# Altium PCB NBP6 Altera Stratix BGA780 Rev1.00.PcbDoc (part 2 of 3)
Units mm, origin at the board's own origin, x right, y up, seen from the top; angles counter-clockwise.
Board outline 69 x 80.99 mm, 6 copper layers (Top Layer, Upper, lower, VCC_PLANE, GND_PLANE, Bottom Layer); 92 components, 279 nets, 1271 pads, 560 vias.
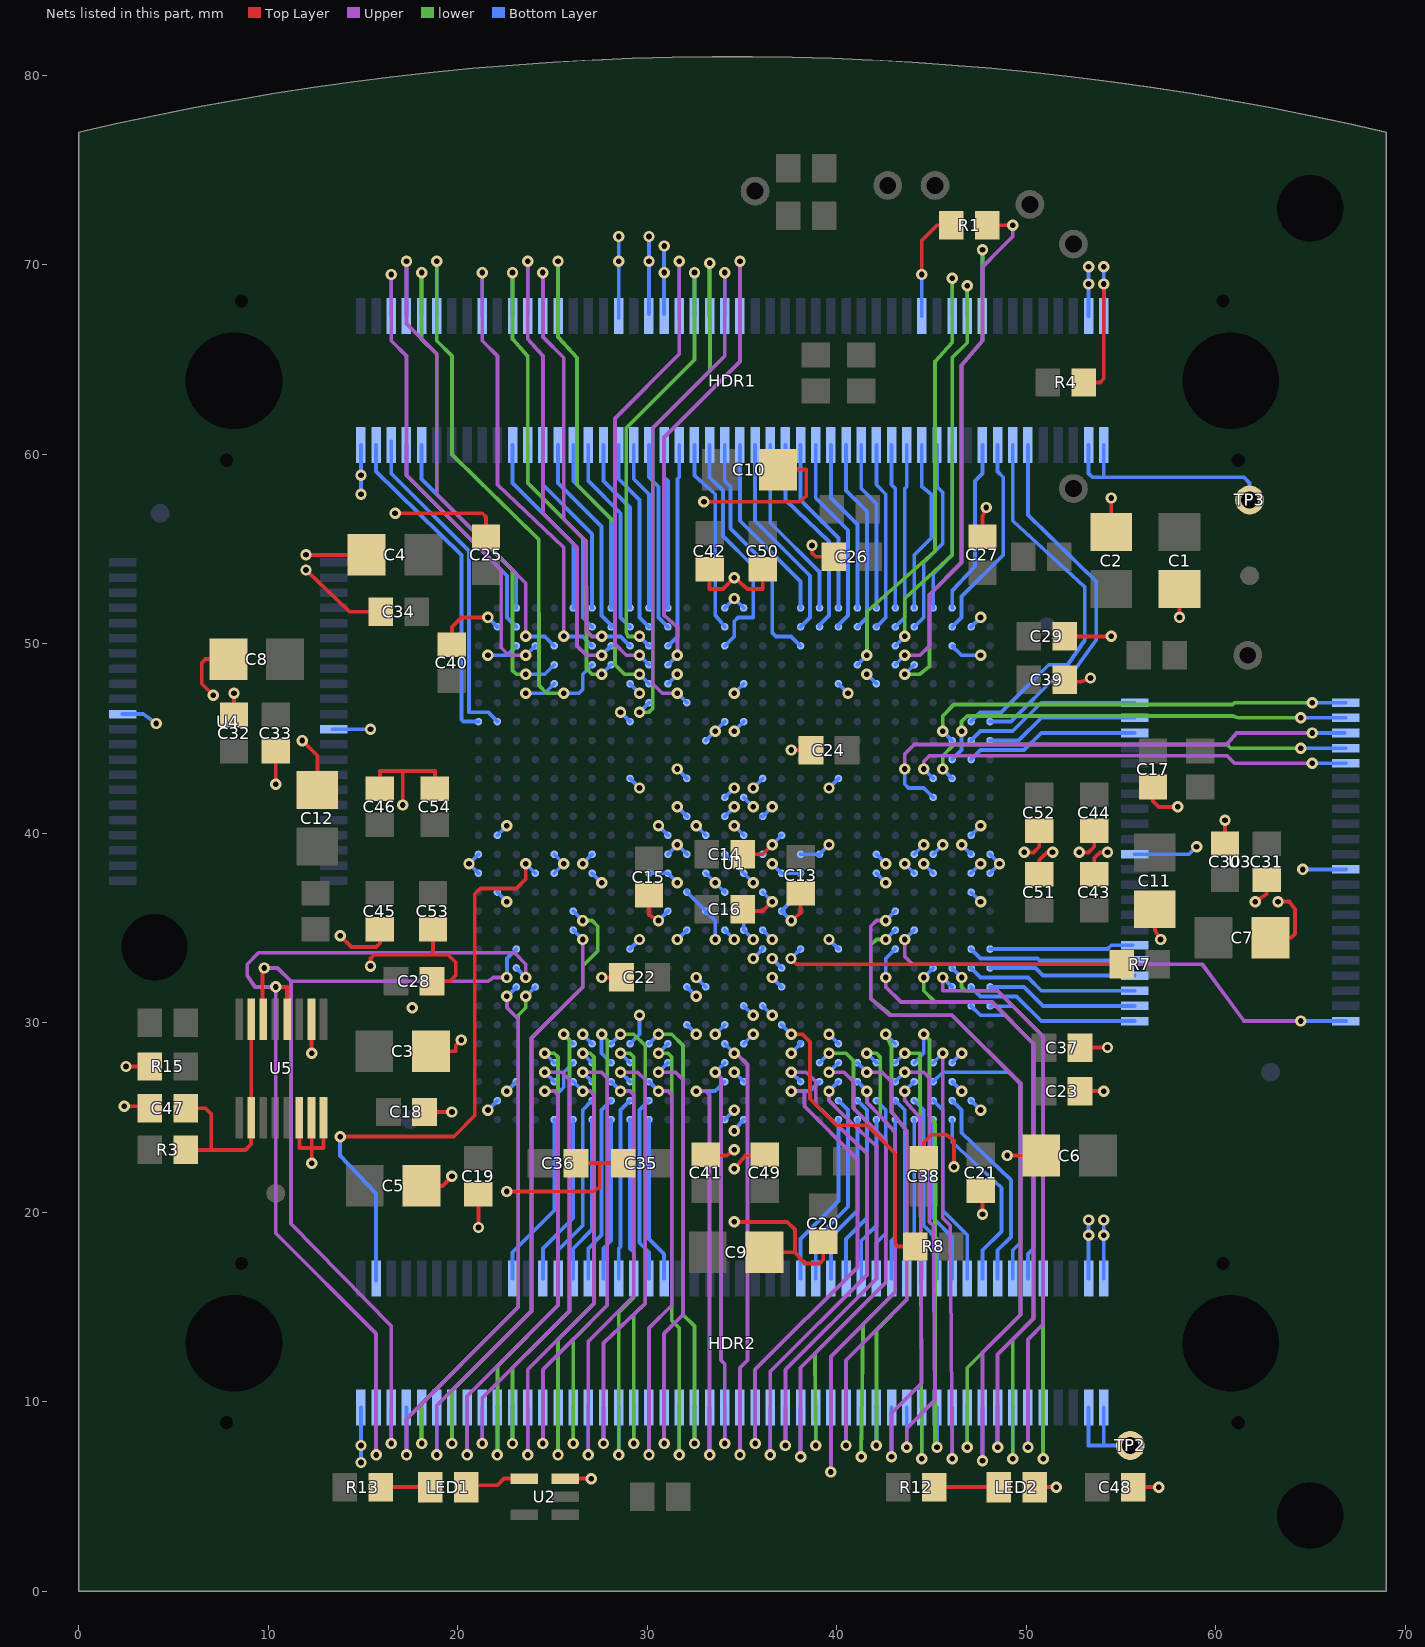
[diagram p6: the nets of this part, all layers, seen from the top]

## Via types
v1: diameter 0.6, hole 0.3, Top Layer to Bottom Layer, 560 vias

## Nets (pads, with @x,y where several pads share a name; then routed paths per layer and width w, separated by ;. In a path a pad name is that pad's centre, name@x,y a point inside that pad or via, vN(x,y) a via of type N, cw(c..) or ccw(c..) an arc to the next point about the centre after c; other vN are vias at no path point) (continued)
GND: C1.2 C2.2 C3.2 C4.2 C5.2 C6.2 C7.2 C8.2 C9.2 C10.2 C11.2 C12.2 C13.2 C14.2 C15.2 C16.2 C17.2 C18.2 C19.2 C20.2 C21.2 C22.2 C23.2 C24.2 C25.2 C26.2 C27.2 C28.2 C29.2 C30.2 C31.2 C32.2 C33.2 C34.2 C35.2 C36.2 C37.2 C38.2 C39.2 C40.2 C41.2 C42.2 C43.2 C44.2 C45.2 C46.2 C47.2 C48.2 C49.2 C50.2 C51.2 C52.2 C53.2 C54.2 HDR1.1 HDR1.36 HDR1.40 HDR1.42 HDR1.98 HDR1.100 HDR2.1 HDR2.98 HDR2.100 LED2.2 R4.2 R15.1 U1.A14 U1.A15 U1.AA12 U1.AA16 U1.AA17 U1.AB13 U1.AB14 U1.AC15 U1.AC17 U1.AD9 U1.AD11 U1.AD14 U1.AD20 U1.AD22 U1.AE3 U1.AF3 U1.AF14 U1.AF26 U1.AG2 U1.AG27 U1.AH14 U1.AH15 U1.B2 U1.B27 U1.C3 U1.C26 U1.E7 U1.E9 U1.E14 U1.E18 U1.E20 U1.E24 U1.G14 U1.G15 U1.G20 U1.H16 U1.K9 U1.K13 U1.K17 U1.K20 U1.L14 U1.L15 U1.M13 U1.M15 U1.M17 U1.N2 U1.N12 U1.N14 U1.N16 U1.N18 U1.N27 U1.P1 U1.P2 U1.P4 U1.P5 U1.P7 U1.P10 U1.P11 U1.P13 U1.P15 U1.P17 U1.P18 U1.P22 U1.P24 U1.P28 U1.R1 U1.R2 U1.R4 U1.R5 U1.R7 U1.R11 U1.R12 U1.R14 U1.R16 U1.R18 U1.R19 U1.R22 U1.R24 U1.R28 U1.T2 U1.T11 U1.T13 U1.T15 U1.T17 U1.T27 U1.U12 U1.U14 U1.U16 U1.U18 U1.V13 U1.V14 U1.V15 U1.V17 U1.W9 U1.W13 U1.W20 U1.Y12 U2.3 U3.12 U3.34 U4.12 U4.34 U5.6 U5.7 U5.8 U5.10 | length 273.2
  Top Layer w0.2: v1(2.4,25.6) C47.2@3.7,25.6 ; v1(2.5,27.7) R15.1@3.75,27.7 ; v1(7.1,47.3) 6.5,47.9 6.5,49 6.7,49.2 C8.2@7.9,49.2 ; C32.2@8.2,46.25 8.2,47.1 v1(8.2,47.4) ; v1@10.4,42.8 C33.2@10.4,44.4 ; U5.6@11.652,25 11.652,23.4 12.9,23.4 12.922,23.422 U5.8@12.922,25 ; v1(11.8,44.9) 12.6,44.1 C12.2@12.6,42.4 ; v1(12,54.7) C4.2@15.2,54.7 ; v1@12.2,53.9 v1(12,53.9) 14.3,51.7 C34.2@15.95,51.7 ; v1(12.3,22.6) U5.7@12.3,25 ; v1(12.3,28.4) 12.287,28.413 U5.10@12.287,30.2 U5.10@12.3,30.213 ; v1(13.8,34.6) 14.4,34 15.7,34 15.9,34.2 C45.2@15.9,35 ; v1@15.4,32.9 15.4,33.4 15.6,33.6 19.5,33.6 19.9,33.2 19.9,32.5 19.6,32.2 C28.2@18.65,32.2 ; C34.2@15.4,51.1 C34.2@16.35,51.1 ; C46.2@15.9,42.35 15.9,43.3 18.8,43.3 C54.2@18.8,42.35 ; v1(16.7,56.9) 21.3,56.9 21.5,56.7 ; v1(17.1,41.5) 17.1,43.3 ; C5.2@18.1,21.4 19.2,21.4 v1(19.7,21.9) ; C18.2@18.2,25.3 v1(19.7,25.3) ; C3.2@18.6,28.5 19.9,28.5 19.9,28.8 v1(20.2,29.1) ; 18.7,33.6 C53.2@18.7,34.95 C53.2@18.7,34.9 ; C40.2@19.7,49.95 19.7,50.9 20.2,51.4 v1(21.6,51.4) ; v1(21.1,19.2) 21.1,20.9 C19.2@21.1,20.95 ; C25.2@21.5,55.85 21.5,56.7 ; 21.5,56.5 21.5,56.7 ; v1(22.6,21.1) 27.1,21.1 27.5,21.3 27.5,22.6 ; U2.3@25.675,5.95 v1(27.05,5.95) ; C36.2@26.25,22.6 27.5,22.6 ; 27.1,22.6 27.5,22.6 ; v1(27.6,32.4) C22.2@28.65,32.4 ; C35.2@28.75,22.6 27.5,22.6 ; C15.2@30.1,36.75 30.1,35.7 v1(30.6,35.4) ; v1(33,57.5) 38,57.5 38.4,57.8 38.4,59.2 C10.2@36.9,59.2 ; C41.2@33.1,23 34.2,23 v1(34.6,23.3) v1@34.6,23.4 ; C42.2@33.3,53.95 33.3,52.9 34,52.9 v1(34.6,53.5) ; v1@34.6,19.6 v1(34.6,19.5) 37.4,19.5 37.8,19.1 37.8,17.9 ; v1(34.6,22.3) 35.2,23 C49.2@36.2,23 ; v1@34.7,53.5 v1(34.6,53.5) ; C16.2@35.05,35.9 36.1,35.9 v1(36.6,36.4) ; C14.2@35.05,38.9 36.1,38.9 v1(36.6,39.4) ; C50.2@36.1,53.95 36.1,52.9 35.3,52.9 v1(34.6,53.5) ; C9.2@36.2,17.9 37.8,17.9 ; v1(37.6,35.4) 38.1,35.8 C13.2@38.1,36.85 ; v1(37.6,44.4) C24.2@38.7,44.4 ; v1(38.7,55.2) 38.7,54.8 38.9,54.6 C26.2@39.85,54.6 ; C20.2@39.3,18.45 39.3,17.5 39.1,17.3 38.3,17.3 37.8,17.9 ; C38.2@44.6,22.85 44.6,23.7 45,24.1 45.8,24.1 46.2,23.8 v1(46.2,22.4) ; v1(47.7,19.9) C21.2@47.7,21 ; C27.2@47.7,55.6 47.7,56.7 v1(47.9,57.2) ; v1(49,23) C6.2@50.7,23 ; v1(49.9,39) 50.4,39 50.7,39.3 C52.2@50.7,40.15 ; LED2.2@50.45,5.5 v1(51.6,5.5) ; C51.2@50.7,37.85 50.7,38.6 51.1,39 v1(51.4,39) ; C39.2@52,48 52.9,48 v1(53.4,48.2) ; C29.2@52.05,50.4 v1@54.2,50.4 ; C37.2@52.4,28.7 v1(54.3,28.7) ; v1(52.8,39) 53.3,39 53.6,39.3 C44.2@53.6,40.2 ; C23.2@52.85,26.4 v1(54.1,26.4) ; R4.2@53.05,63.8 53.9,63.8 54.1,64 v1(54.1,69) ; C43.2@53.6,37.85 53.6,38.7 53.9,39 v1(54.3,39) ; C2.2@54.5,55.9 v1(54.5,57.7) ; C48.2@55.6,5.5 v1(57,5.5) ; C17.2@56.7,42.4 56.7,41.7 57,41.4 v1(58,41.4) ; C11.2@56.8,36 56.8,34.9 v1(57.1,34.4) ; v1(58.1,51.4) C1.2@58.1,52.9 ; C30.2@60.5,39.4 v1(60.5,40.7) ; v1(62.1,36.4) 62.7,36.8 C31.2@62.7,37.55 ; C7.2@62.9,34.5 64,34.5 64.2,34.7 64.2,36 63.9,36.4 v1(63.3,36.4)
  Upper w0.2: v1(27.05,5.95) v1@27.1,6
  Bottom Layer w0.2: U4.34@2.3,46.3 3.4,46.3 v1(4.1,45.8) ; U4.12@13.4,45.5 v1(15.4,45.5) ; v1(14.9,6.8) v1(14.9,7.7) HDR2.1@14.9,9.7 ; v1(14.9,57.9) HDR1.1@14.9,60.5 ; U1.R28@21.1,37.9 v1(20.6,38.4) U1.P28@21.1,38.9 ; v1(21.6,25.4) U1.AG27@22.1,25.9 ; v1(21.6,49.4) 22.6,49.4 U1.C26@23.1,49.9 ; v1(21.6,51.4) U1.B27@22.1,50.9 ; U1.T27@22.1,36.9 v1(22.6,36.4) ; U1.N27@22.1,39.9 v1(22.6,40.4) ; v1(22.6,26.4) U1.AF26@23.1,26.9 ; v1(23.6,47.4) 24.6,47.4 U1.E24@25.1,47.9 ; U1.R24@25.1,37.9 v1(25.6,38.4) U1.P24@25.1,38.9 ; v1(26.6,29.4) U1.AD22@27.1,28.9 ; v1(26.6,38.4) U1.P22@27.1,38.9 ; U1.R22@27.1,37.9 v1(27.6,37.4) ; HDR1.36@28.5,67.2 v1(28.5,71.5) ; v1(28.6,46.4) U1.G20@29.1,45.9 ; U1.AD20@29.1,28.9 29.6,29.4 v1(29.6,30.4) ; U1.W20@29.1,33.9 v1(29.6,34.4) ; U1.K20@29.1,42.9 v1(29.6,42.4) ; U1.E20@29.1,47.9 v1(29.6,47.4) ; U1.R19@30.1,37.9 U1.R18@31.1,37.9 v1(31.6,37.4) ; HDR1.40@30.1,67.4 v1(30.1,71.5) ; v1(30.6,35.4) U1.U18@31.1,35.9 ; v1(30.6,40.4) U1.N18@31.1,39.9 ; HDR1.42@30.9,67.4 v1(30.9,71) ; U1.P18@31.1,38.9 v1(31.6,39.4) U1.P17@32.1,38.9 ; U1.E18@31.1,47.9 v1(31.6,48.4) ; v1(31.6,34.4) U1.V17@32.1,34.9 ; v1(31.6,41.4) U1.M17@32.1,40.9 ; v1(31.6,43.4) U1.K17@32.1,42.9 ; U1.AC17@32.1,29.9 v1(32.6,29.4) ; U1.AA17@32.1,31.9 v1(32.6,31.4) ; U1.T17@32.1,37 U1.T17@32.1,36.9 U1.U16@33.1,35.9 ; v1(32.6,32.4) U1.AA16@33.1,31.9 ; v1(32.6,40.4) U1.N16@33.1,39.9 ; U1.U16@33.1,35.8 U1.U16@33.1,35.9 ; U1.R16@33.1,37.9 v1(33.6,37.4) U1.T15@34.1,36.9 U1.T15@34.1,37 ; U1.H16@33.1,44.9 v1(33.6,45.4) U1.G15@34.1,45.9 ; v1(33.6,29.4) U1.AC15@34.1,29.9 ; v1(33.6,34.4) 33.6,35.3 33.6,35.4 U1.U16@33.1,35.9 ; U1.AH15@34.1,24.9 v1(34.6,25.4) ; U1.V15@34.1,34.9 v1(34.6,34.4) ; U1.P15@34.1,38.9 U1.R14@35.1,37.9 v1@35.5,37.5 ; U1.M15@34.1,40.9 v1(34.6,41.4) ; U1.L15@34.1,41.9 v1(34.6,42.4) ; U1.A15@34.1,51.9 v1(34.6,52.4) U1.A14@35.1,51.9 ; v1(34.6,24.3) U1.AH14@35.1,24.9 ; v1(34.6,27.4) U1.AF14@35.1,26.9 ; v1(34.6,40.4) U1.N14@35.1,39.9 ; v1(34.6,45.4) U1.G14@35.1,45.9 ; v1(34.6,47.4) U1.E14@35.1,47.9 ; U1.AD14@35.1,28.9 v1(35.6,29.4) ; U1.AB14@35.1,30.9 v1(35.6,30.4) ; U1.U14@35.1,35.9 U1.V14@35.1,34.9 v1(35.6,34.4) ; U1.L14@35.1,41.9 v1(35.6,41.4) ; v1(35.6,33.4) U1.W13@36.1,33.9 ; v1(35.6,42.4) U1.K13@36.1,42.9 ; U1.M13@36,40.9 U1.M13@36.1,40.9 v1(36.6,41.4) ; U1.AB13@36.1,30.9 v1(36.6,30.4) ; U1.V13@36.1,34.9 v1(36.6,34.4) ; U1.T13@36.1,36.9 v1(36.6,36.4) ; U1.P13@36.1,38.9 v1(36.6,39.4) ; v1(36.6,32.4) U1.AA12@37.1,31.9 ; v1(36.6,33.4) U1.Y12@37.1,32.9 ; v1(36.6,38.4) U1.R12@37.1,37.9 ; v1@36.6,39.5 v1(36.6,39.4) ; U1.N12@37,39.8 v1(36.6,39.4) ; U1.R12@37.2,37.9 U1.R12@37.1,37.9 ; v1(37.6,28.4) U1.AD11@38.1,28.9 ; v1(37.6,35.4) U1.U12@37.1,35.9 U1.T11@38.1,36.9 ; U1.AD11@38,28.9 U1.AD11@38.1,29 ; U1.R11@38,37.9 U1.R11@38.1,37.9 ; U1.P11@38.1,38.9 U1.P10@39.1,38.9 ; U1.R11@38.2,37.9 U1.R11@38.1,37.9 ; U1.P10@39.1,38.8 U1.P10@39.1,38.9 ; v1(39.6,29.4) U1.AD9@40.1,28.9 ; v1(39.6,34.4) U1.W9@40.1,33.9 ; v1(39.6,39.4) U1.P10@39.1,38.9 ; v1(39.6,42.4) U1.K9@40.1,42.9 ; U1.E9@40.1,47.9 v1(40.6,47.4) ; v1(41.6,48.4) U1.E7@42.1,47.9 ; U1.R7@42.1,37.9 v1(42.6,37.4) ; U1.P7@42.1,38.9 v1(42.6,38.4) ; v1(43.6,38.4) U1.R5@44.1,37.9 ; U1.P5@44.1,38.9 v1(44.6,39.4) ; v1(44.6,38.4) U1.R4@45.1,37.9 ; U1.P4@45.1,38.9 v1(45.6,39.4) ; U1.AF3@46.1,26.9 v1(46.6,26.4) ; U1.AE3@46.1,27.9 v1(46.6,28.4) ; U1.C3@46.2,49.9 U1.C3@46.1,49.9 46.6,49.4 v1(47.6,49.4) ; v1(46.6,39.4) U1.P2@47.1,38.9 U1.P2@47.1,39 ; U1.AG2@47.1,25.9 v1(47.6,25.4) ; U1.T2@47.1,36.9 v1(47.6,36.4) ; U1.R2@47.1,37.9 v1(47.6,38.4) ; U1.N2@47.1,39.9 v1(47.6,40.4) ; U1.B2@47.1,50.9 v1(47.6,51.4) ; U1.R1@48.1,37.9 v1(48.6,38.4) U1.P1@48.1,38.9 ; HDR2.98@53.3,16.5 v1(53.3,19.6) ; HDR1.98@53.3,67.3 v1(53.3,69.9) ; HDR2.100@54.1,16.5 v1(54.1,19.6) ; HDR1.100@54.1,67.4 v1(54.1,69.9) ; U3.34@55.725,38.9 58.6,38.9 v1(59,39.3) ; v1(64.6,38.1) U3.12@66.9,38.1 ; U1.W13@36.1,33.9 36.1,34 U1.W13@36.1,33.9 ; U1.R12@37.1,37.9 U1.R11@38.1,37.9 ; U1.N12@37,39.9 U1.N12@37.1,39.9 U1.N12@37,39.9
  other v1: 53.3,18.8 54.1,18.8 17.6,30.8 15.4,33 35.6,37.4 10.4,42.6 54.5,50.4 14.9,58.9 53.3,69 30.9,69.6 28.5,70.2 30.1,70.2
GREEN0: HDR1.10 U1.D24 | length 27.7
  lower w0.2: v1(18.1,69.6) 18.1,66.1 18.9,65.3 18.9,57.9 22.9,53.9 22.9,48.6 23.1,48.4 v1(23.6,48.4)
  Bottom Layer w0.2: HDR1.10@18.1,67.4 v1(18.1,69.6) ; v1(23.6,48.4) 24.6,48.4 U1.D24@25.1,48.9
GREEN1: HDR1.12 U1.D22 | length 31.6
  lower w0.2: v1(18.9,70.2) 18.9,66 19.7,65.2 19.7,60 24.283,55.517 24.3,47.8 24.7,47.4 v1(25.6,47.4)
  Bottom Layer w0.2: HDR1.12@18.9,67.3 v1(18.9,70.2) ; v1(25.6,47.4) 26.4,47.4 26.6,47.6 26.6,48.4 U1.D22@27.1,48.9
HDRIVE: HDR1.18 U1.C22 | length 25
  Upper w0.2: v1(21.3,69.6) 21.3,66 22.1,65.2 22.1,58.4 25.6,55.1 v1(25.6,50.4)
  Bottom Layer w0.2: HDR1.18@21.3,67.3 v1(21.3,69.6) ; v1(25.6,50.4) 26.6,50.4 U1.C22@27.1,49.9
INIT_DONE: R7.2 U1.W11 | length 18.3
  Top Layer w0.2: v1(37.592,33.401) 37.893,33.1 R7.2@55.05,33.1
  Bottom Layer w0.2: v1(37.592,33.401) v1@37.633,33.441 ; v1@37.637,33.437 U1.W11@38.1,33.9
IO0: HDR2.7 U1.AA26 | length 30.1
  Upper w0.2: v1(17.3,7.2) 17.3,9.1 23.2,15 23.2,30.2 22.6,30.8 v1(22.6,31.4)
  Bottom Layer w0.2: v1(17.3,7.2) HDR2.7@17.3,9.7 ; v1(22.6,31.4) U1.AA26@23.1,31.9
IO1: HDR2.9 U1.AA25 | length 28.4
  lower w0.2: v1(18.1,7.8) 18.1,9.9 23.2,15 23.2,15.3 23.2,30.4 23.6,30.8 v1(23.6,31.4)
  Bottom Layer w0.2: v1(18.1,7.8) HDR2.9@18.1,9.6 ; v1(23.6,31.4) U1.AA25@24.1,31.9
IO2: HDR2.11 U1.V23 | length 33.6
  Upper w0.2: v1(18.9,7.2) 18.9,9.8 23.9,14.8 23.9,29.2 26.6,31.9 v1(26.6,34.4)
  Bottom Layer w0.2: v1(18.9,7.2) HDR2.11@18.9,9.7 ; U1.V23@26.1,34.9 v1(26.6,34.4)
IO3: HDR2.13 U1.U23 | length 34
  lower w0.2: v1(19.7,7.8) 19.7,10.6 23.9,14.8 23.9,29.2 26.6,31.9 26.6,33 27.4,33.8 27.4,35.1 27.1,35.4 v1(26.6,35.4)
  Bottom Layer w0.2: v1(19.7,7.8) HDR2.13@19.7,9.7 ; U1.U23@26.1,35.9 v1(26.6,35.4)
IO4: HDR2.15 U1.AE23 | length 26.9
  Upper w0.2: v1(20.5,7.2) 20.5,10.3 25.3,15.1 25.3,26.2 25.1,26.4 v1(24.6,26.4)
  Bottom Layer w0.2: v1(20.5,7.2) HDR2.15@20.5,9.7 ; v1(24.6,26.4) 25.4,26.4 25.6,26.6 25.6,27.4 U1.AE23@26.1,27.9
IO5: HDR2.17 U1.AF24 | length 25.2
  Upper w0.2: v1(21.3,7.8) 21.3,10.2 25.9,14.8 25.9,27 25.5,27.4 v1(24.6,27.4)
  Bottom Layer w0.2: v1(21.3,7.8) HDR2.17@21.3,9.7 ; v1(24.6,27.4) U1.AF24@25.1,26.9
IO6: HDR2.19 U1.AE24 | length 26.3
  lower w0.2: v1(22.1,7.2) 22.1,11.9 25.3,15.1 25.3,28.2 25.1,28.4 v1(24.6,28.4)
  Bottom Layer w0.2: v1(22.1,7.2) HDR2.19@22.1,9.7 ; v1(24.6,28.4) U1.AE24@25.1,27.9
IO7: HDR2.21 U1.AD23 | length 25.6
  lower w0.2: v1(22.9,7.8) 22.9,11.8 25.9,14.8 25.9,29.1 v1(25.6,29.4)
  Bottom Layer w0.2: v1(22.9,7.8) HDR2.21@22.9,9.7 ; v1(25.6,29.4) U1.AD23@26.1,28.9
IO8: HDR2.23 U1.AF23 | length 24.3
  Upper w0.2: v1(23.7,7.2) 23.7,11.7 27.2,15.2 27.2,26.2 27,26.4 v1(26.6,26.4)
  Bottom Layer w0.2: v1(23.7,7.2) HDR2.23@23.7,9.7 ; U1.AF23@26.1,26.9 v1(26.6,26.4)
IO9: HDR2.25 U1.AF22 | length 24.7
  Upper w0.2: v1(24.5,7.8) 24.5,11.7 27.9,15.1 27.9,27.1 27.6,27.4 v1(26.6,27.4)
  Bottom Layer w0.2: v1(24.5,7.8) HDR2.25@24.5,9.7 ; v1(26.6,27.4) U1.AF22@27.1,26.9
IO10: HDR2.27 U1.AE22 | length 25.8
  lower w0.2: v1(25.3,7.2) 25.3,13.3 27.2,15.2 27.2,28.2 27,28.4 v1(26.6,28.4)
  Bottom Layer w0.2: v1(25.3,7.2) HDR2.27@25.3,9.8 ; v1(26.6,28.4) U1.AE22@27.1,27.9
IO11: HDR2.29 U1.AE21 | length 26.1
  lower w0.2: v1(26.1,7.8) 26.1,13.3 27.9,15.1 27.9,29.1 v1(27.6,29.4)
  Bottom Layer w0.2: v1(26.1,7.8) HDR2.29@26.1,9.7 ; v1(27.6,29.4) 27.6,28.4 U1.AE21@28.1,27.9
IO12: HDR2.31 U1.AF21 | length 24.1
  Upper w0.2: v1(26.9,7.2) 26.9,13.2 29.3,15.6 29.3,26.2 29.1,26.4 v1(28.6,26.4)
  Bottom Layer w0.2: v1(26.9,7.2) HDR2.31@26.9,9.8 ; U1.AF21@28.1,26.9 v1(28.6,26.4)
IO13: HDR2.33 U1.AF20 | length 24.2
  Upper w0.2: v1(27.7,7.8) 27.7,13.1 29.9,15.2 29.9,27 29.5,27.4 v1(28.6,27.4)
  Bottom Layer w0.2: v1(27.7,7.8) HDR2.33@27.7,9.7 ; v1(28.6,27.4) U1.AF20@29.1,26.9
IO14: HDR2.35 U1.AE20 | length 25.3
  lower w0.2: v1(28.5,7.2) 28.5,14.7 29.3,15.5 29.3,28.2 29.1,28.4 v1(28.6,28.4)
  Bottom Layer w0.2: v1(28.5,7.2) HDR2.35@28.5,9.7 ; v1(28.6,28.4) U1.AE20@29.1,27.9
IO15: HDR2.37 U1.AD21 | length 25.5
  lower w0.2: v1(28.6,29.4) 29.3,29.4 29.9,28.8 29.9,15.2 29.3,14.6 v1(29.3,7.8)
  Bottom Layer w0.2: U1.AD21@28.1,28.9 v1(28.6,29.4) ; v1(29.3,7.8) HDR2.37@29.3,9.8
IO16: HDR2.39 U1.AF19 | length 23.5
  Upper w0.2: v1(30.1,7.2) 30.1,13.9 31.3,15.1 31.3,26.2 31.1,26.4 v1(30.6,26.4)
  Bottom Layer w0.2: v1(30.1,7.2) HDR2.39@30.1,9.7 ; U1.AF19@30.1,26.9 v1(30.6,26.4)
IO17: HDR2.41 U1.AE18 | length 23.7
  Upper w0.2: v1(30.6,27.4) 31.5,27.4 31.9,27 31.9,14.6 30.9,13.6 v1(30.9,7.8)
  Bottom Layer w0.2: v1(30.6,27.4) U1.AE18@31.1,27.9 ; v1(30.9,7.8) HDR2.41@30.9,9.7
IO18: HDR2.43 U1.AD18 | length 25.2
  lower w0.2: v1(30.6,28.4) 31.1,28.4 31.3,28.2 31.3,14.3 31.7,13.9 v1(31.7,7.2)
  Bottom Layer w0.2: v1(30.6,28.4) U1.AD18@31.1,28.9 ; v1(31.7,7.2) HDR2.43@31.7,9.7
IO19: HDR2.45 U1.AD19 | length 25.4
  lower w0.2: v1(30.6,29.4) 31.3,29.4 31.9,28.8 31.9,14.6 32.5,14 v1(32.5,7.8)
  Bottom Layer w0.2: U1.AD19@30.1,28.9 v1(30.6,29.4) ; v1(32.5,7.8) HDR2.45@32.5,9.7
IO20: HDR2.47 U1.AF15 | length 24
  Upper w0.2: v1(32.6,26.4) 33.1,26.4 33.3,26.2 v1(33.3,7.2)
  Bottom Layer w0.2: v1(32.6,26.4) 33.6,26.4 U1.AF15@34.1,26.9 ; v1(33.3,7.2) HDR2.47@33.3,9.7
IO21: HDR2.49 U1.AE15 | length 22.4
  Upper w0.2: v1(33.6,27.4) 33.9,27.1 33.9,12.2 34.1,12 v1(34.1,7.8)
  Bottom Layer w0.2: v1(33.6,27.4) U1.AE15@34.1,27.9 ; v1(34.1,7.8) HDR2.49@34.1,9.7
IO22: HDR2.51 U1.AD15 | length 24.9
  Upper w0.2: v1(34.6,28.4) 34.7,28.4 35.3,27.8 35.3,12.2 34.9,11.8 v1(34.9,7.2)
  Bottom Layer w0.2: U1.AD15@34.1,28.9 v1(34.6,28.4) ; v1(34.9,7.2) HDR2.51@34.9,9.7
IO23: HDR2.53 U1.AF10 | length 26.3
  Upper w0.2: v1(35.7,7.8) 35.7,11.7 41.1,17.1 41.1,20.1 41.1,22.8 38.3,25.6 38.3,26.3 38.2,26.4 v1(37.6,26.4)
  Bottom Layer w0.2: v1@35.6,7.8 35.7,7.9 HDR2.53@35.7,9.7 ; v1(37.6,26.4) 38.6,26.4 U1.AF10@39.1,26.9
IO24: HDR2.55 U1.AF11 | length 31.1
  Upper w0.2: v1(36.5,7.2) 36.5,11.6 41.6,16.7 41.6,23.1 ; v1(37.6,27.4) 38.4,27.4 38.9,26.9 38.9,25.7 41.6,23.1 ; 41.6,19.7 41.6,23.1
  Bottom Layer w0.2: v1(36.5,7.2) HDR2.55@36.5,9.7 ; v1(37.6,27.4) U1.AF11@38.1,26.9
IO25: HDR2.57 U1.AF9 | length 24.5
  Upper w0.2: v1(37.3,7.7) 37.3,11.7 42.1,16.5 42.1,23.5 40.3,25.2 39.6,25.9 v1(39.6,26.4)
  Bottom Layer w0.2: v1(37.3,7.7) HDR2.57@37.3,9.7 ; v1(39.6,26.4) U1.AF9@40.1,26.9
IO26: HDR2.59 U1.AE9 | length 27.2
  Upper w0.2: v1(38.1,7.1) 38.1,11.8 42.6,16.3 42.6,18.9 42.6,23.8 40.9,25.5 40.9,26.9 40.4,27.4 v1(39.6,27.4)
  Bottom Layer w0.2: v1(38.1,7.1) HDR2.59@38.1,9.7 ; v1(39.6,27.4) U1.AE9@40.1,27.9
IO27: HDR2.61 U1.AE10 | length 31.6
  lower w0.2: v1(38.9,7.7) 38.869,12.569 42.6,16.3 42.6,23.8 ; v1(39.6,28.4) 40.5,28.4 40.9,28 40.9,25.5 42.6,23.8 ; 42.6,18.9 42.6,23.8
  Bottom Layer w0.2: v1(38.9,7.7) HDR2.61@38.9,9.7 ; U1.AE10@39.1,27.9 v1(39.6,28.4)
IO28: HDR2.63 U1.AF8 | length 30
  Upper w0.2: v1(39.7,6.3) 39.7,12.4 43.1,15.8 ; v1(41.6,26.4) 41.6,25.8 42.3,25.1 43.1,24.2 43.1,15.8 ; 43.1,18.7 43.1,15.8
  Bottom Layer w0.2: 39.7,7.2 v1(39.7,6.3) HDR2.63@39.7,9.7 ; U1.AF8@41.1,26.9 v1(41.6,26.4)
IO29: HDR2.65 U1.AE8 | length 25
  Upper w0.2: v1@40.5,7.7 40.5,12.2 43.7,15.4 43.7,24.3 42.9,25.3 42.9,26.9 42.4,27.4 v1(41.6,27.4)
  Bottom Layer w0.2: v1(40.5,7.7) HDR2.65@40.5,9.7 ; U1.AE8@41.1,27.9 v1(41.6,27.4)
IO30: HDR2.67 U1.AE7 | length 26.3
  lower w0.2: v1(41.3,7.1) 41.4,14.1 43.1,15.8 43.1,18.7 43.1,24.2 42.3,25.1 42.3,28.2 42.1,28.4 v1(41.6,28.4)
  Bottom Layer w0.2: v1@41.3,7 v1(41.3,7.1) HDR2.67@41.3,9.7 ; v1(41.6,28.4) U1.AE7@42.1,27.9
IO31: HDR2.69 U1.AD6 | length 25.4
  lower w0.2: v1(42.1,7.7) 42.1,13.8 43.7,15.4 43.7,24.3 42.9,25.3 42.9,28.7 v1(42.6,29.4)
  Bottom Layer w0.2: v1(42.1,7.7) HDR2.69@42.1,9.7 ; v1(42.6,29.4) U1.AD6@43.1,28.9
IO32: HDR2.71 U1.AF5 | length 23.6
  Upper w0.2: v1(42.9,7.1) 42.9,9.4 44.5,11 44.4,25 43.6,25.9 v1(43.6,26.4)
  Bottom Layer w0.2: v1(42.9,7.1) HDR2.71@42.9,9.7 ; v1(43.6,26.4) U1.AF5@44.1,26.9
IO33: HDR2.73 U1.AF6 | length 29.7
  Upper w0.2: v1(43.6,27.4) 44.6,27.4 44.9,27.1 44.9,25.1 44.9,24.8 ; v1(43.7,7.6) 43.7,8.6 45.2,10.1 45.1,19.3 44.9,19.5 ; 44.9,19.5 44.9,24.8 ; 44.9,19.5 44.9,24.8
  Bottom Layer w0.2: U1.AF6@43.1,26.9 v1(43.6,27.4) ; v1(43.7,7.6) HDR2.73@43.7,9.7
IO34: HDR2.75 U1.AE6 | length 25.6
  lower w0.2: v1(43.6,28.4) 44.4,28.4 v1(44.5,7)
  Bottom Layer w0.2: U1.AE6@43.1,27.9 v1(43.6,28.4) ; v1(44.5,7) HDR2.75@44.5,9.7
IO35: HDR2.77 U1.AE5 | length 25.8
  lower w0.2: v1(44.6,29.4) 44.9,29.1 44.9,25.1 45.2,24.7 v1@45.2,7.6
  Bottom Layer w0.2: U1.AE5@44.1,27.9 44.6,28.4 v1(44.6,29.4) ; v1(45.3,7.6) HDR2.77@45.3,9.7
JIOA0: HDR1.3 U1.G28 | length 17.3
  Bottom Layer w0.2: HDR1.3@15.7,60.5 15.7,59.1 20.2,54.7 20.2,52.8 20.2,46 20.3,45.9 U1.G28@21.1,45.9
JIOA1: HDR1.5 U1.G27 | length 18
  Bottom Layer w0.2: HDR1.5@16.5,60.4 HDR1.5@16.5,60.5 16.5,60.7 16.5,59 20.6,54.9 20.6,46.4 21.6,46.4 U1.G27@22.1,45.9
JIOA2: HDR1.7 U1.B26 | length 12
  Bottom Layer w0.2: HDR1.7@17.3,60.5 17.3,59.1 17.3,58.9 22.6,53.6 22.6,52.6 22.6,51.4 U1.B26@23.1,50.9
JIOA3: HDR1.9 U1.A26 | length 11.1
  Bottom Layer w0.2: HDR1.9@18.1,60.5 18.1,59.1 18.1,59.3 18.1,58.7 23.1,53.7 U1.A26@23.1,51.9
JIOB0: HDR1.83 U1.A3 | length 9.2
  Bottom Layer w0.2: U1.A3@46.1,51.9 46.1,52.8 47.3,54.1 47.3,58.3 47.3,58.6 47.7,59 HDR1.83@47.7,60.5
JIOB1: HDR1.85 U1.B3 | length 10.8
  Bottom Layer w0.2: U1.B3@46.1,50.9 46.6,51.4 46.6,52.5 48.8,54.7 48.8,58.8 48.5,59.1 HDR1.85@48.5,60.5
JIOB2: HDR1.87 U1.G2 | length 20
  Bottom Layer w0.2: U1.G2@47.1,45.9 47.6,46.4 48.7,46.4 49.1,46.8 51.2,48.9 52.2,48.9 53.1,50.2 53.1,53 ; HDR1.87@49.3,60.5 49.3,56.5 53.1,53 ; 53.1,52.9 53.1,53
JIOB3: HDR1.89 U1.G1 | length 19.4
  Bottom Layer w0.2: U1.G1@48.1,45.9 49.2,45.9 51.7,48.4 52.4,48.4 53.7,50.2 53.7,53.3 50.1,56.8 HDR1.89@50.1,60.5
KBCLOCK: HDR1.22 U1.D21 | length 26.4
  lower w0.2: v1(22.9,69.6) 22.9,66.1 23.7,65.2 23.7,58.5 26.781,55.419 26.8,48.7 27.1,48.4 v1(27.6,48.4)
  Bottom Layer w0.2: HDR1.22@22.9,67.3 v1(22.9,69.6) ; v1(27.6,48.4) U1.D21@28.1,48.9
KBDATA: HDR1.24 U1.C21 | length 26.5
  Upper w0.2: v1(23.7,70.2) 23.7,66.1 24.5,65.2 24.5,56.9 26.3,55.1 26.3,49.9 26.8,49.4 v1(27.6,49.4)
  Bottom Layer w0.2: HDR1.24@23.7,67.3 v1(23.7,70.2) ; v1(27.6,49.4) U1.C21@28.1,49.9
LCD_BCKL: HDR2.22 U1.AH24 | length 9.3
  Bottom Layer w0.2: HDR2.22@22.9,16.5 22.9,17.9 25.1,20.1 U1.AH24@25.1,24.9
LCD_E: HDR2.26 U1.AH23 | length 9.1
  Bottom Layer w0.2: HDR2.26@24.5,16.5 24.5,18.1 26.1,19.7 U1.AH23@26.1,24.9
LED0: HDR2.60 U1.AH9 | length 9.2
  Bottom Layer w0.2: HDR2.60@38.1,16.5 38.1,18.6 40.1,20.6 U1.AH9@40.1,24.9
LED1: HDR2.62 U1.AG9 | length 10.3
  Bottom Layer w0.2: HDR2.62@38.9,16.5 38.9,18.6 40.6,20.3 40.6,25.4 U1.AG9@40.1,25.9
LED2: HDR2.64 U1.AH8 | length 9
  Bottom Layer w0.2: HDR2.64@39.7,16.5 39.7,18.7 41.1,20.1 U1.AH8@41.1,24.9
LED3: HDR2.66 U1.AG8 | length 10.2
  Bottom Layer w0.2: HDR2.66@40.5,16.6 HDR2.66@40.5,16.5 40.5,18.6 41.6,19.7 41.6,25.4 U1.AG8@41.1,25.9
LED4: HDR2.68 U1.AH7 | length 8.7
  Bottom Layer w0.2: HDR2.68@41.3,16.5 41.3,18.5 42.1,19.3 U1.AH7@42.1,24.9
LED5: HDR2.70 U1.AG7 | length 9.8
  Bottom Layer w0.2: HDR2.70@42.1,16.5 42.1,18.4 42.6,18.9 42.6,25.4 U1.AG7@42.1,25.9
LED6: HDR2.72 U1.AH6 | length 8.5
  Bottom Layer w0.2: HDR2.72@42.9,16.5 42.9,18.5 43.1,18.7 U1.AH6@43.1,24.9
LED7: HDR2.74 U1.AG6 | length 9.7
  Bottom Layer w0.2: U1.AG6@43.1,25.8 U1.AG6@43.1,25.9 43.6,25.4 43.6,18.7 43.7,18.5 HDR2.74@43.7,16.5
MOUSECLOCK: HDR1.26 U1.C20 | length 24.9
  Upper w0.2: v1(24.5,69.6) 24.5,66.2 25.6,65.1 25.6,56.6 26.781,55.419 26.799,50.7 ; 26.8,50.7 27.1,50.4 v1(27.6,50.4)
  Bottom Layer w0.2: HDR1.26@24.5,67.2 v1(24.5,69.6) ; v1(27.6,50.4) 28.6,50.4 U1.C20@29.1,49.9
MOUSEDATA: HDR1.28 U1.E19 | length 27.6
  lower w0.2: v1(25.3,70.2) 25.3,66.2 26.3,65.1 26.3,58.4 28.3,56.4 28.3,48.9 28.8,48.4 v1(29.6,48.4)
  Bottom Layer w0.2: HDR1.28@25.3,67.3 v1(25.3,70.2) ; v1(29.6,48.4) U1.E19@30.1,47.9
NetC47_1: C47.1 R3.2 U5.2 U5.15 | length 13.4
  Top Layer w0.2: R3.2@5.65,23.3 8.8,23.3 9.1,23.6 ; C47.1@5.65,25.5 6.7,25.5 7,25.2 7,23.3 ; 9.103,23.6 9.112,24.612 9.112,24.9 U5.15@9.112,30.1
NetHDR1_97: HDR1.97 HDR1.99 TP3.1 | length 12.8
  Bottom Layer w0.2: HDR1.97@53.3,60.5 53.3,59 53.5,58.8 55.5,58.8 61.5,58.8 61.8,58.5 TP3.1@61.8,57.6 ; 54.1,58.8 HDR1.99@54.1,60.5
NetHDR2_97: HDR2.97 HDR2.99 TP2.1 | length 6.2
  Bottom Layer w0.2: HDR2.97@53.3,9.7 53.3,7.7 54.1,7.7 ; HDR2.99@54.1,9.7 54.1,7.7 ; TP2.1@55.5,7.7 54.1,7.7
NetLED1_1: LED1.1 R13.2 | length 2.6
  Top Layer w0.2: R13.2@15.95,5.5 LED1.1@18.55,5.5
NetLED1_2: LED1.2 U2.4 | length 3.2
  Top Layer w0.2: LED1.2@20.5,5.6 22.1,5.6 22.45,5.95 U2.4@23.525,5.95
NetLED2_1: LED2.1 R12.2 | length 3.4
  Top Layer w0.2: R12.2@45.15,5.5 LED2.1@48.6,5.5
NEXUS_TCK: HDR1.82 U1.C6 | length 22.2
  lower w0.2: v1(43.6,50.4) 43.6,52.4 46.1,54.7 46.1,65.1 46.9,65.9 v1(46.9,68.9)
  Bottom Layer w0.2: U1.C6@43.1,49.9 v1(43.6,50.4) ; HDR1.82@46.9,67.3 v1(46.9,68.9)
NEXUS_TDI: HDR1.84 U1.D5 | length 28.8
  lower w0.2: v1(43.6,48.4) 44.4,48.4 44.9,48.8 44.9,52.6 46.6,54.3 46.6,64.7 47.7,66 v1(47.7,70.8)
  Bottom Layer w0.2: v1(43.6,48.4) U1.D5@44.1,48.9 ; HDR1.84@47.7,67.3 47.7,70.3 v1(47.7,70.8)
NEXUS_TDO: HDR1.76 R1.1 | length 6
  Top Layer w0.2: v1(44.5,69.5) 44.5,71.3 45.3,72.1 R1.1@46.15,72.1
  Bottom Layer w0.2: HDR1.76@44.5,67.3 v1(44.5,69.5)
NEXUS_TDO#: R1.2 U1.D6 | length 27.4
  Top Layer w0.2: R1.2@48.05,72.1 v1(49.3,72.1)
  Upper w0.2: v1(43.6,49.4) 44.4,49.4 44.9,49.9 44.9,52.6 46.6,54.3 46.6,64.7 47.7,66 47.7,69.9 48.6,70.8 49.3,71.5 v1(49.3,72.1)
  Bottom Layer w0.2: U1.D6@43.1,48.9 v1(43.6,49.4)
NEXUS_TMS: HDR1.80 U1.D8 | length 24.5
  lower w0.2: v1(41.6,49.4) 41.6,51.7 45.2,54.9 45.2,64.9 46.1,65.9 v1(46.1,69.3)
  Bottom Layer w0.2: U1.D8@41.1,48.9 v1(41.6,49.4) ; HDR1.80@46.1,67.4 v1(46.1,69.3)
PORSEL: R8.1 U1.AC12 | length 16.4
  Top Layer w0.2: v1(37.6,29.4) 38.2,29.4 38.6,29 38.6,26 40,24.6 41.6,24.6 43.1,23.1 43.1,18.4 43.2,18.2 R8.1@44.15,18.2
  Bottom Layer w0.2: U1.AC12@37.1,29.9 v1(37.6,29.4)
RAM0_DATA0: HDR2.42 U1.AH19 | length 8.7
  Bottom Layer w0.2: U1.AH19@30.1,24.9 30.1,18.6 30.9,17.8 HDR2.42@30.9,16.5
RAM0_DATA1: HDR2.40 U1.AG19 | length 9.8
  Bottom Layer w0.2: HDR2.40@30.1,16.5 30.1,17.9 29.6,18.4 29.6,25.4 U1.AG19@30.1,25.9
RAM0_DATA2: HDR2.38 U1.AH20 | length 8.5
  Bottom Layer w0.2: U1.AH20@29.1,24.9 29.1,18.1 29.3,17.9 HDR2.38@29.3,16.5
RAM0_DATA3: HDR2.36 U1.AG20 | length 9.6
  Bottom Layer w0.2: HDR2.36@28.5,16.5 28.5,18.1 28.6,18.2 28.6,25.4 U1.AG20@29.1,25.9
RAM0_DATA4: HDR2.34 U1.AH21 | length 8.6
  Bottom Layer w0.2: HDR2.34@27.7,16.5 27.7,18.1 28.1,18.5 U1.AH21@28.1,24.9
RAM0_DATA5: HDR2.32 U1.AG21 | length 9.9
  Bottom Layer w0.2: HDR2.32@26.9,16.5 26.9,18.1 27.6,18.8 27.6,25.4 U1.AG21@28.1,25.9
RAM0_DATA6: HDR2.30 U1.AH22 | length 8.8
  Bottom Layer w0.2: HDR2.30@26.1,16.5 26.1,18.1 27.1,19.1 U1.AH22@27.1,24.9
RAM0_DATA7: HDR2.28 U1.AG22 | length 10.1
  Bottom Layer w0.2: HDR2.28@25.3,16.5 25.3,18 26.6,19.3 26.6,25.4 U1.AG22@27.1,25.9
RAM0_OE: HDR1.41 U1.A18 | length 8.7
  Bottom Layer w0.2: HDR1.41@30.9,60.5 30.9,58.8 31.1,58.6 U1.A18@31.1,51.9
RAM0_WE: HDR1.79 U1.A4 | length 9
  Bottom Layer w0.2: U1.A4@45.1,51.9 45.1,52.6 45.1,53.7 46.1,54.7 HDR1.79@46.1,60.5
RAM1_DATA0: HDR1.45 U1.B15 | length 10.3
  Bottom Layer w0.2: HDR1.45@32.5,60.5 32.5,58.9 33.6,57.9 33.6,51.5 U1.B15@34.1,50.9
RAM1_DATA1: HDR1.49 U1.C11 | length 12.7
  Bottom Layer w0.2: HDR1.49@34.1,60.5 34.1,58.6 34.4,58.3 34.4,56.1 36.6,53.9 36.6,50.6 36.8,50.4 37.6,50.4 U1.C11@38.1,49.9
RAM1_DATA2: HDR1.53 U1.B11 | length 11
  Bottom Layer w0.2: HDR1.53@35.7,60.5 35.7,56.5 38.6,53.6 38.6,51.4 U1.B11@38.1,50.9
RAM1_DATA3: HDR1.57 U1.B10 | length 10.8
  Bottom Layer w0.2: HDR1.57@37.3,60.5 37.3,57.6 39.6,55.4 39.6,51.5 39.1,51 U1.B10@39.1,50.9
RAM1_DATA4: HDR1.55 U1.A10 | length 9.6
  Bottom Layer w0.2: 36.5,56.4 39.1,53.8 U1.A10@39.1,51.9 ; 36.5,56.5 HDR1.55@36.5,60.5
RAM1_DATA5: HDR1.51 U1.A11 | length 9.9
  Bottom Layer w0.2: HDR1.51@34.9,60.5 34.9,56.5 38.1,53.3 U1.A11@38.1,51.9
RAM1_DATA6: HDR1.47 U1.C15 | length 12.6
  Bottom Layer w0.2: HDR1.47@33.3,60.5 33.3,58.8 34,58.1 34,55.7 35.6,54.1 35.6,51.4 34.8,51.4 34.6,51.2 34.6,50.4 U1.C15@34.1,49.9
RAM1_DATA7: HDR1.43 U1.C18 | length 10.8
  Bottom Layer w0.2: U1.C18@31.1,49.9 31.6,50.4 31.6,58.7 31.7,58.8 HDR1.43@31.7,60.5
RAM1_OE: HDR1.39 U1.B18 | length 10
  Bottom Layer w0.2: HDR1.39@30.1,60.5 30.1,58.8 30.6,58.3 30.6,51.4 U1.B18@31.1,50.9
RAM1_WE: HDR1.61 U1.B9 | length 10.5
  Bottom Layer w0.2: HDR1.61@38.9,60.5 38.9,57.7 40.6,56 40.6,51.5 40.1,51 U1.B9@40.1,50.9
RAM_ADDR0: HDR1.21 U1.A23 | length 9.9
  Bottom Layer w0.2: HDR1.21@22.9,60.5 22.9,58.5 26.1,55.3 26.1,52.5 U1.A23@26.1,51.9
RAM_ADDR1: HDR1.25 U1.A22 | length 9.7
  Bottom Layer w0.2: HDR1.25@24.5,60.5 24.5,58.4 27.1,55.8 27.1,52.5 U1.A22@27.1,51.9
RAM_ADDR2: HDR1.29 U1.A21 | length 9.4
  Bottom Layer w0.2: HDR1.29@26.1,60.5 26.1,58.6 28.1,56.6 28.1,52.5 U1.A21@28.1,51.9
RAM_ADDR3: HDR1.33 U1.A20 | length 9.2
  Bottom Layer w0.2: HDR1.33@27.7,60.5 27.7,58.6 29.1,57.2 29.1,52.5 U1.A20@29.1,51.9
RAM_ADDR4: HDR1.65 U1.B8 | length 10.3
  Bottom Layer w0.2: HDR1.65@40.5,60.5 40.5,58.1 41.6,57 41.6,52.6 41.6,51.4 U1.B8@41.1,50.9
RAM_ADDR5: HDR1.69 U1.B7 | length 10.1
  Bottom Layer w0.2: U1.B7@42.1,51 U1.B7@42.1,50.9 42.6,51.4 42.6,57.9 42.1,58.4 HDR1.69@42.1,60.5
RAM_ADDR6: HDR1.73 U1.B6 | length 9.8
  Bottom Layer w0.2: U1.B6@43.1,50.9 43.6,51.4 43.6,58.2 43.7,58.3 HDR1.73@43.7,60.5
RAM_ADDR7: HDR1.77 U1.B5 | length 10.3
  Bottom Layer w0.2: U1.B5@44.1,50.9 44.6,51.4 44.6,52.6 44.6,54.3 45.6,55.3 45.6,57.5 45.6,58 45.3,58.3 HDR1.77@45.3,60.5
RAM_ADDR8: HDR1.75 U1.A5 | length 9.2
  Bottom Layer w0.2: U1.A5@44.1,51.9 44.1,52.6 44.1,54.7 45,55.6 45,57.9 44.5,58.3 HDR1.75@44.5,60.5
RAM_ADDR9: HDR1.71 U1.A6 | length 8.7
  Bottom Layer w0.2: HDR1.71@42.9,60.5 42.9,58.4 43.1,58.2 43.1,52.6 U1.A6@43.1,51.9
RAM_ADDR10: HDR1.67 U1.A7 | length 8.9
  Bottom Layer w0.2: HDR1.67@41.3,60.5 41.3,58.2 42.1,57.4 U1.A7@42.1,51.9
RAM_ADDR11: HDR1.63 U1.A8 | length 9.2
  Bottom Layer w0.2: HDR1.63@39.7,60.5 39.7,57.7 41.1,56.3 41.1,52.6 U1.A8@41.1,51.9
RAM_ADDR12: HDR1.59 U1.A9 | length 9.4
  Bottom Layer w0.2: HDR1.59@38.1,60.5 38.1,57.6 40.1,55.6 U1.A9@40.1,51.9
RAM_ADDR13: HDR1.35 U1.B19 | length 10.3
  Bottom Layer w0.2: HDR1.35@28.5,60.5 28.5,58.7 29.6,57.6 29.6,51.4 U1.B19@30.1,50.9
RAM_ADDR14: HDR1.31 U1.B20 | length 10.7
  Bottom Layer w0.2: HDR1.31@26.9,60.5 26.9,58.6 28.6,56.9 28.6,52.3 ; 28.6,52.5 28.6,51.4 U1.B20@29.1,50.9
RAM_ADDR15: HDR1.27 U1.B21 | length 10.8
  Bottom Layer w0.2: HDR1.27@25.3,60.5 25.3,58.5 27.6,56.2 27.6,51.5 28.1,51 U1.B21@28.1,50.9
RAM_ADDR16: HDR1.23 U1.B22 | length 11
  Bottom Layer w0.2: HDR1.23@23.7,60.5 23.7,58.5 26.6,55.6 26.6,52.5 26.6,51.4 U1.B22@27.1,50.9
RAM_CS: HDR1.37 U1.A19 | length 8.9
  Bottom Layer w0.2: HDR1.37@29.3,60.5 29.3,58.7 30.1,57.9 U1.A19@30.1,51.9
RED0: HDR1.6 U1.C25 | length 26.5
  Upper w0.2: v1(16.5,69.5) 16.5,66 17.3,65.2 17.3,58.9 22.3,53.9 22.3,49.8 22.7,49.4 v1(23.6,49.4)
  Bottom Layer w0.2: HDR1.6@16.5,67.3 v1(16.5,69.5) ; v1(23.6,49.4) U1.C25@24.1,49.9
RED1: HDR1.8 U1.C24 | length 27
  Upper w0.2: v1(17.3,70.2) 17.3,66.9 18.9,65.3 18.9,57.9 23.6,53.2 v1(23.6,50.4)
  Bottom Layer w0.2: HDR1.8@17.3,67.3 v1(17.3,70.2) ; v1(23.6,50.4) 24.6,50.4 U1.C24@25.1,49.9
REF_CLK: HDR2.4 U1.R25 | length 32.3
  Top Layer w0.2: v1(13.8,24) 19.8,24 19.9,24.1 20.9,25.1 20.9,27.6 20.904,36.804 21.2,37.1 23.1,37.1 23.6,37.6 v1(23.6,38.4)
  Bottom Layer w0.2: 13.8,23.141 13.8,23 ; v1(13.8,24) 13.8,23 ; HDR2.4@15.7,16.4 15.7,21 13.8,23 ; v1(23.6,38.4) U1.R25@24.1,37.9
SCL: HDR2.5 U1.W26 U5.14 | length 46
  Top Layer w0.2: U5.14@9.7,30.2 9.7,32.6 v1(9.8,32.9)
  Upper w0.2: v1(9.8,32.9) 10.5,32.9 11.2,32.2 ; v1(16.5,7.8) 16.5,14 11.2,19.4 11.2,32.2 ; v1(22.6,32.4) 21.9,32.4 21.6,32.2 11.2,32.2
  Bottom Layer w0.2: v1(16.5,7.8) HDR2.5@16.5,9.7 ; v1(22.6,32.4) 22.6,33.4 U1.W26@23.1,33.9
SDA: HDR2.3 U1.Y26 U5.12 | length 50.8
  Top Layer w0.2: v1(10.4,31.9) 11,31.9 11.017,30.2 U5.12@11.017,30.1
  Upper w0.2: v1(15.7,7.2) 15.7,13.6 10.4,18.9 v1(10.4,31.9) 9.3,31.9 8.9,32.5 8.9,33.1 9.5,33.7 23,33.7 23.6,33.1 v1(23.6,32.4)
  Bottom Layer w0.2: v1(15.7,7.2) HDR2.3@15.7,9.7 ; U1.Y26@23.1,32.9 v1(23.6,32.4)
SP0: HDR2.79 U1.AE4 | length 25
  Upper w0.2: v1(45.6,28.4) 45.6,19.7 46,19.3 v1(46.1,7)
  Bottom Layer w0.2: U1.AE4@45.1,27.9 v1(45.6,28.4) ; v1(46.1,7) HDR2.79@46.1,9.7
SP1: HDR2.81 U1.V6 | length 36.7
  lower w0.2: v1(42.6,34.4) 42.1,34.4 41.8,34.1 41.8,31.3 42.9,30.4 46.1,30.4 49.7,26.8 49.7,14.6 46.9,11.8 v1(46.9,7.6)
  Bottom Layer w0.2: v1(42.6,34.4) U1.V6@43.1,34.9 ; v1(46.9,7.6) HDR2.81@46.9,9.8
SP2: HDR2.83 U1.U6 | length 38.7
  Upper w0.2: v1(42.6,35.4) 42.1,35.4 41.8,35.1 41.8,31.3 42.8,30.4 46.1,30.4 49.7,26.8 49.7,14.6 47.7,12.6 v1(47.7,6.9)
  Bottom Layer w0.2: v1(42.6,35.4) U1.U6@43.1,35.9 ; v1(47.7,6.9) HDR2.83@47.7,9.7
SP3: HDR2.85 U1.W6 | length 35.5
  Upper w0.2: v1(42.6,32.4) 42.6,31.9 43.4,31.1 48.2,31.1 50.4,28.9 50.4,14.4 48.5,12.5 v1(48.5,7.6)
  Bottom Layer w0.2: v1(42.6,32.4) 42.6,33.4 U1.W6@43.1,33.9 ; v1(48.5,7.6) HDR2.85@48.5,9.8
SP4: HDR2.87 U1.Y4 | length 33.4
  lower w0.2: v1(44.6,32.4) 44.6,31.7 45.2,31.1 48.2,31.1 50.4,28.9 50.4,14.4 49.3,13.3 v1(49.3,7)
  Bottom Layer w0.2: v1(44.6,32.4) U1.Y4@45.1,32.9 ; v1(49.3,7) HDR2.87@49.3,9.7
SP5: HDR2.89 U1.AA3 | length 31.8
  Upper w0.2: v1(45.6,32.4) 45.6,31.7 48.5,31.7 50.9,29.3 50.9,14.1 50.1,13.3 v1(50.1,7.6)
  Bottom Layer w0.2: v1(45.6,32.4) U1.AA3@46.1,31.9 ; v1(50.1,7.6) HDR2.89@50.1,9.7
SP6: HDR2.91 U1.Y3 | length 31.6
  lower w0.2: v1(46.6,32.4) 46.6,31.9 46.8,31.7 48.5,31.7 50.9,29.3 v1(50.9,7)
  Bottom Layer w0.2: U1.Y3@46.1,32.9 v1(46.6,32.4) ; v1(50.9,7) HDR2.91@50.9,9.7
SP7: HDR2.92 U1.AB1 | length 16.2
  Bottom Layer w0.2: U1.AB1@48.127,30.873 49.322,30.878 50.9,29.3 50.9,16.6 HDR2.92@50.9,16.5
SP8: HDR2.90 U1.AB2 | length 16.7
  Bottom Layer w0.2: U1.AB2@47.1,30.9 47.6,30.4 48.9,30.4 50.4,28.9 50.4,18.1 50.1,17.8 HDR2.90@50.1,16.5
SP9: HDR2.88 U1.AF4 | length 15.5
  Bottom Layer w0.2: U1.AF4@45.1,26.9 45.6,27.4 49.1,27.4 49.7,26.8 49.7,18.4 49.3,18 HDR2.88@49.3,16.5
SP10: HDR2.86 U1.AG3 | length 11
  Bottom Layer w0.2: U1.AG3@46.1,25.9 46.6,25.4 46.6,24.2 49.2,21.7 49.2,18.7 48.5,18 HDR2.86@48.5,16.5
SP11: HDR2.84 U1.AH3 | length 10
  Bottom Layer w0.2: U1.AH3@46.1,24.9 46.1,23.7 48.7,21.3 48.7,19 47.7,18 HDR2.84@47.7,16.5
SP12: HDR2.82 U1.AG4 | length 10.1
  Bottom Layer w0.2: U1.AG4@45.1,25.9 45.6,25.4 45.6,20.1 ; 45.6,20.1 46.9,18.8 HDR2.82@46.9,16.5
SP13: HDR2.80 U1.AH4 | length 8.8
  Bottom Layer w0.2: U1.AH4@45.1,24.9 45.1,19.7 46.1,18.7 HDR2.80@46.1,16.5
SP14: HDR2.78 U1.AG5 | length 9.9
  Bottom Layer w0.2: U1.AG5@44.1,25.9 44.6,25.4 44.6,19.3 45.3,18.6 HDR2.78@45.3,16.5
SP15: HDR2.76 U1.AH5 | length 8.6
  Bottom Layer w0.2: U1.AH5@44.1,24.9 44.1,18.9 44.5,18.5 HDR2.76@44.5,16.5
SPI_CLK: HDR1.46 U1.C19 | length 24.3
  lower w0.2: v1(29.6,50.4) 29,50.4 28.9,50.6 28.9,61.4 32.5,65 v1(32.5,69.6)
  Bottom Layer w0.2: v1(29.6,50.4) U1.C19@30.1,49.9 ; HDR1.46@32.5,67.3 v1(32.5,69.6)
SPI_DIN: HDR1.44 U1.D19 | length 26.9
  Upper w0.2: v1(29.6,49.4) 28.9,49.4 28.3,50 28.3,61.9 31.7,65.3 v1(31.7,70.2)
  Bottom Layer w0.2: v1(29.6,49.4) U1.D19@30.1,48.9 ; HDR1.44@31.7,67.2 v1(31.7,70.2)
SPI_DOUT: HDR1.50 U1.F17 | length 27.8
  Upper w0.2: v1(31.6,47.4) 30.8,47.4 30.3,47.9 30.3,50.9 30.3,61.4 34.1,65.2 v1(34.1,69.6)
  Bottom Layer w0.2: v1(31.6,47.4) U1.F17@32.1,46.9 ; HDR1.50@34.1,67.3 v1(34.1,69.6)
SPI_MODE: HDR1.52 U1.D18 | length 27.1
  Upper w0.2: v1(31.6,49.4) 31.6,50.1 31.6,50.9 ; 31.6,50.2 31.6,50.9 ; v1(34.9,70.2) 34.9,64.9 30.9,60.9 30.9,51.5 31.6,50.9
  Bottom Layer w0.2: U1.D18@31.1,48.9 v1(31.6,49.4) ; HDR1.52@34.9,67.3 v1(34.9,70.2)
SPI_SEL: HDR1.48 U1.F19 | length 29
  lower w0.2: v1(29.6,46.4) 30.1,46.4 30.3,46.6 30.3,50.9 30.3,61.4 33.315,64.415 v1(33.3,70.1)
  Bottom Layer w0.2: v1(29.6,46.4) U1.F19@30.1,46.9 ; HDR1.48@33.3,67.3 v1(33.3,70.1)
SRAM0_A0: U1.K4 U3.5 | length 23.7
  Upper w0.2: v1(44.6,43.4) 44.6,43.8 44.9,44.1 60.6,44.1 61,43.7 v1(65.1,43.7)
  Bottom Layer w0.2: v1(44.6,43.4) U1.K4@45.1,42.9 ; v1(65.1,43.7) U3.5@66.9,43.7
SRAM0_A1: U1.K3 U3.4 | length 23
  lower w0.2: v1(45.6,43.4) 45.6,44.1 46.2,44.7 60.6,44.7 60.8,44.5 v1(64.5,44.5)
  Bottom Layer w0.2: v1(45.6,43.4) U1.K3@46.1,42.9 ; v1(64.5,44.5) U3.4@66.875,44.5
SRAM0_A2: U1.L4 U3.3 | length 27.1
  Upper w0.2: v1(43.6,43.4) 43.6,44.2 44.1,44.7 60.6,44.7 61.1,45.3 v1(65.1,45.3)
  Bottom Layer w0.2: v1(43.6,43.4) 43.6,42.6 43.8,42.4 44.6,42.4 U1.L4@45.1,41.9 ; v1(65.1,45.3) U3.3@66.8,45.3
SRAM0_A3: U1.J3 U3.2 | length 22.7
  lower w0.2: v1(46.6,45.4) 46.6,45.9 46.9,46.2 60.9,46.2 61.2,46.1 v1(64.5,46.1)
  Bottom Layer w0.2: U1.J3@46.1,43.9 46.6,44.4 v1(46.6,45.4) ; v1@64.4,46.1 v1(64.5,46.1) U3.2@66.875,46.1
SRAM0_A4: U1.H3 U3.1 | length 23.1
  lower w0.2: v1(45.6,45.4) 45.6,46.2 46.2,46.8 60.9,46.8 61,46.9 v1(65.1,46.9)
  Bottom Layer w0.2: v1(45.6,45.4) U1.H3@46.1,44.9 ; v1(65.1,46.9) U3.1@66.875,46.9
SRAM0_A5: U1.H2 U3.44 | length 9.5
  Bottom Layer w0.2: U1.H2@47.1,44.9 47.6,45.4 49.3,45.4 50.8,46.9 U3.44@55.725,46.9
SRAM0_A6: U1.H1 U3.43 | length 8.1
  Bottom Layer w0.2: U1.H1@48.1,44.9 49.6,44.9 50.8,46.1 U3.43@55.725,46.1
SRAM0_A7: U1.J2 U3.42 | length 9.2
  Bottom Layer w0.2: U1.J2@47.1,43.9 47.6,44.4 49.9,44.4 50.8,45.3 U3.42@55.725,45.3
SRAM0_A8: U1.W1 U3.28 | length 7.6
  Bottom Layer w0.2: U1.W1@48.1,33.9 54.3,33.9 54.5,34.1 U3.28@55.625,34.1
SRAM0_A9: U1.W2 U3.27 | length 8.9
  Bottom Layer w0.2: U1.W2@47.1,33.9 47.6,33.4 50.6,33.4 50.7,33.3 U3.27@55.725,33.3
SRAM0_A10: U1.Y1 U3.26 | length 7.8
  Bottom Layer w0.2: U1.Y1@48.1,32.9 50.5,32.9 50.9,32.5 55.625,32.5 U3.26@55.725,32.5
SRAM0_A11: U1.Y2 U3.25 | length 9.1
  Bottom Layer w0.2: U1.Y2@47.1,32.9 47.6,32.4 50.1,32.4 50.8,31.7 U3.25@55.725,31.7
SRAM0_A12: U1.AA1 U3.24 | length 8
  Bottom Layer w0.2: U1.AA1@48.1,31.9 49.9,31.9 50.9,30.9 U3.24@55.725,30.9
SRAM0_A13: U1.AA2 U3.23 | length 9.4
  Bottom Layer w0.2: U1.AA2@47.1,31.9 47.6,31.4 49.5,31.4 50.8,30.1 U3.23@55.725,30.1
SRAM0_A14: U1.V5 U3.22 | length 26.6
  Upper w0.2: v1(43.6,34.4) 43.6,33.5 44,33.1 59.3,33.1 61.5,30.1 v1(64.5,30.1)
  Bottom Layer w0.2: v1(43.6,34.4) U1.V5@44.1,34.9 ; v1(64.5,30.1) U3.22@66.9,30.1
